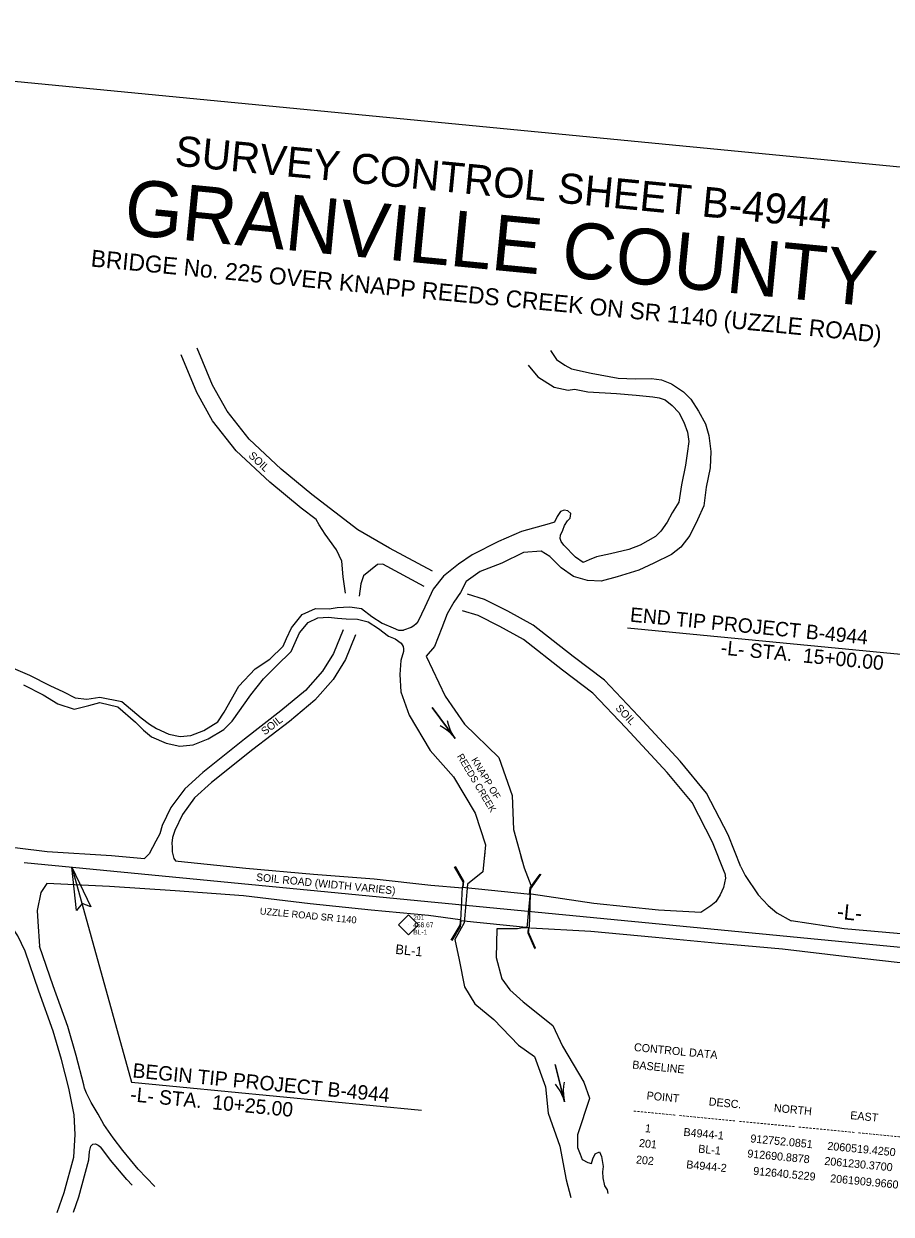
# Model space of a CAD drawing. Extents: x 2060504 to 2061945, y 912229 to 913160.
# Drawn here: x 2061030 to 2061482, y 912540 to 913160 of the extents above; entities that cross this region are included whole.
import ezdxf

# ---------------------------------------------------------------- set-up
doc = ezdxf.new("R2010")
doc.units = 0
for name, color, linetype in [('COGO Default Chain', 7, 'Continuous'), ('CTL Sheet Border CELL', 7, 'Continuous'), ('CTL Sheet Text', 7, 'Continuous'), ('CTL Supplemental Horizontal and Vertical CELL', 7, 'Continuous'), ('CTL Supplemental Horizontal and Vertical Cogo Comment', 7, 'Continuous'), ('CTL Supplemental Horizontal and Vertical Cogo Elevation', 7, 'Continuous'), ('CTL Supplemental Horizontal and Vertical Cogo Number', 7, 'Continuous'), ('CTL Supplemental Horizontal and Vertical Text', 7, 'Continuous'), ('Default', 7, 'Continuous'), ('Exist Horizontal Alignment', 7, 'Continuous'), ('Exist Hydro Jurisdictional Stream or Body of Water', 7, 'Continuous'), ('Exist Hydro Stream or Body of Water', 7, 'Continuous'), ('Exist PHM Water Shape', 7, 'Continuous'), ('Exist Roads Soil', 7, 'Continuous'), ('Exist Roads Soil Text', 7, 'Continuous'), ('Exist Structure Major Bridge WW', 7, 'Continuous'), ('Exist Structure Major Deck Tunnel Box Culvert', 7, 'Continuous'), ('Prop Terminator CELL', 7, 'Continuous'), ('Sheet Data Field CELL', 7, 'Continuous')]:
    doc.layers.add(name, color=color, linetype=linetype)

# ---------------------------------------------------------------- blocks, each defined once
blk = doc.blocks.new('EXIST HYDRO RIVER FLOW ARROW')
at = {"layer": 'Default'}
blk.add_line((0, 0), (0, 0), dxfattribs=at)
blk.add_lwpolyline([(0, 0.04575), (0.03775, 0.03), (0.07725, 0.01725), (0.118, 0.00775), (0.159, 0.0015), (0.2, 0), (-0.2, 0), (0.2, 0), (0.159, -0.0015), (0.118, -0.00775), (0.07725, -0.01725), (0.03775, -0.03), (0, -0.04575)], dxfattribs=at)

msp = doc.modelspace()

# ---------------------------------------------------------------- linework, layer by layer
at = {"layer": 'COGO Default Chain'}
msp.add_line((2061030.33, 912723.42), (2061621.2, 912666.3), dxfattribs=at)
at = {"layer": 'CTL Sheet Border CELL'}
msp.add_lwpolyline([(2061883, 913047.03), (2060714.54, 913159.97), (2060635.47, 912342.05), (2061803.94, 912229.1)], close=True, dxfattribs=at)
at = {"layer": 'CTL Supplemental Horizontal and Vertical CELL'}
msp.add_line((2061230.37, 912690.89), (2061230.37, 912690.89), dxfattribs=at)
msp.add_lwpolyline([(2061225.16, 912690.91), (2061230.4, 912696.15), (2061235.65, 912690.9), (2061230.41, 912685.66)], close=True, dxfattribs=at)
at = {"layer": 'Exist Horizontal Alignment'}
msp.add_line((2061030.33, 912723.42), (2061621.2, 912666.3), dxfattribs=at)
at = {"layer": 'Exist Hydro Jurisdictional Stream or Body of Water'}
for points in [[(2061304.42, 912989.92), (2061307.54, 912985.21), (2061311.82, 912982.35), (2061315.34, 912980.44), (2061325.46, 912978.15), (2061339.51, 912975.44), (2061348.55, 912975.2), (2061356.88, 912975.38), (2061362.21, 912974.71), (2061367.28, 912972.49), (2061373.57, 912968.41), (2061377.35, 912964.63), (2061381.47, 912958.32), (2061385.06, 912951.64), (2061386.79, 912945.66), (2061387.76, 912937.35), (2061387.52, 912928.81), (2061385.39, 912918.75), (2061384.14, 912909.07), (2061380.97, 912901.67), (2061376.92, 912893.61), (2061372.18, 912887.44), (2061367.4, 912883.66), (2061358.23, 912879.2), (2061350.28, 912875.6), (2061339.1, 912872.15), (2061330.73, 912869.8), (2061323.62, 912870.25), (2061316.37, 912872.25), (2061309.97, 912876.82), (2061304.07, 912882.6), (2061299.52, 912885.49), (2061290.35, 912884.82), (2061279.03, 912879.14), (2061267.8, 912874.87), (2061260.5, 912869.71), (2061257.49, 912863.9), (2061254.01, 912858.95), (2061250.54, 912852.73), (2061247.8, 912845.5), (2061243.96, 912835.84), (2061239.71, 912830.79), (2061249.44, 912809.94)], [(2061292.78, 912982.22), (2061297.82, 912976.25), (2061306.31, 912970.77), (2061313.49, 912969.29), (2061316.86, 912969.71), (2061323.87, 912968.32), (2061338.79, 912967.46), (2061349.03, 912966.7), (2061357.56, 912965.7), (2061360.86, 912965.19), (2061363.99, 912964.18), (2061367.63, 912961.35), (2061371.24, 912957.71), (2061373.7, 912952.61), (2061375.6, 912947.36), (2061376.34, 912942.47), (2061375.54, 912936.27), (2061374.61, 912930.26), (2061372.52, 912920.03), (2061371.17, 912911), (2061367.65, 912905.32), (2061365.03, 912900.55), (2061361.82, 912895.77), (2061358.97, 912893.01), (2061351.07, 912888.53), (2061345.07, 912886.25), (2061335.63, 912883.97), (2061328.39, 912882.57), (2061324.51, 912880.84), (2061321.36, 912879.57), (2061317.46, 912882.26), (2061311.25, 912888.61), (2061309.97, 912890.39), (2061309.4, 912892.04), (2061309.62, 912893.77), (2061310.71, 912896.31), (2061311.59, 912898.82), (2061313.14, 912901.22), (2061314.63, 912902.66), (2061314.88, 912905), (2061313.41, 912906.43), (2061311.48, 912906.71), (2061309.57, 912906.04), (2061307.82, 912903.42), (2061306.45, 912900.55), (2061303.59, 912899.73), (2061289.23, 912895.74), (2061277.29, 912890.45), (2061263.65, 912883.57), (2061256.5, 912878.71), (2061248.58, 912872.42), (2061243.24, 912865.71), (2061238.87, 912856.23), (2061235.44, 912849.05), (2061234.38, 912847.57)], [(2061014.35, 912828.84), (2061033.04, 912820.93), (2061043.62, 912815.46), (2061050.74, 912812.26), (2061056.95, 912809.15), (2061062.9, 912808.46), (2061069.77, 912809.46), (2061081.18, 912807.13), (2061091.23, 912798.73), (2061095.59, 912795.43), (2061099.24, 912793.06), (2061105.74, 912790.15), (2061111.58, 912788.95), (2061117.19, 912789.51), (2061123.89, 912792.12), (2061131.22, 912796.59), (2061134.39, 912801.56), (2061142.12, 912815.13), (2061150.54, 912824.12), (2061158.29, 912829.28), (2061165.13, 912836.06), (2061166.88, 912839.91), (2061169.48, 912845.61), (2061175.05, 912852.43), (2061182.09, 912855.52), (2061189.19, 912855.36), (2061193.24, 912856.16), (2061199.82, 912856.53), (2061205.99, 912855.6), (2061211.3, 912851.5), (2061216.75, 912847.89), (2061222.49, 912845.48), (2061225.31, 912844.38), (2061227.89, 912844.39)], [(2061029.97, 912815.9), (2061040.31, 912810.63), (2061047.78, 912806.01), (2061056.31, 912803.11), (2061064.07, 912805.08), (2061069.72, 912806.67), (2061079.13, 912804.41), (2061088.22, 912796.47), (2061092.42, 912792.25), (2061096.62, 912788.82), (2061104.21, 912785.41), (2061111.33, 912783.96), (2061118.36, 912784.66), (2061126.09, 912787.68), (2061134.25, 912792.65), (2061138.64, 912796.89), (2061148.33, 912810.68), (2061154.87, 912819.05), (2061161.76, 912825.76), (2061169.26, 912833.2), (2061171.37, 912837.86), (2061173.71, 912842.98), (2061178.13, 912848.38), (2061183.31, 912850.66), (2061188.82, 912851.09), (2061193.53, 912850.53), (2061198.04, 912850.21), (2061203.92, 912850.06), (2061209.45, 912848.69), (2061214.73, 912845.17), (2061219.97, 912841.13), (2061223.47, 912839.79), (2061226.62, 912837.47)], [(2061226.62, 912837.47), (2061227.59, 912835.83), (2061227.91, 912834.64), (2061227.77, 912833.17)], [(2061227.77, 912833.17), (2061226.42, 912828.49), (2061225.86, 912821.31), (2061226.47, 912812.15), (2061230.85, 912800.08)], [(2061249.44, 912809.94), (2061259.59, 912795.35), (2061277.43, 912778.04), (2061284.45, 912758.16), (2061285.07, 912740.61), (2061290.6, 912720.54), (2061294.17, 912711.64), (2061292.06, 912689.41), (2061289.73, 912689.28), (2061287.13, 912688.9), (2061276.35, 912688.89), (2061276.03, 912673.92), (2061279.1, 912662.87), (2061283.26, 912657.14), (2061290.13, 912650.75), (2061305.62, 912638.46), (2061310.54, 912627.68), (2061321.66, 912609), (2061324.73, 912600.71)], [(2061230.85, 912800.08), (2061241.79, 912781.69), (2061253.93, 912767.88), (2061265.22, 912749.03), (2061270.49, 912732.47), (2061269.15, 912718.44), (2061261.19, 912712.07), (2061259.41, 912692.02), (2061254.6, 912683.23), (2061256.75, 912672.67), (2061259.51, 912658.65), (2061265.02, 912649.85), (2061274.93, 912641.7), (2061287.62, 912628.21), (2061296.1, 912622.37), (2061301.68, 912606.52), (2061303.06, 912592.92)], [(2061270.13, 912728.64), (2061269.82, 912725.38)], [(2061288.98, 912726.44), (2061289.8, 912723.45)], [(2061324.73, 912600.56), (2061318.39, 912581.55), (2061318.36, 912575.07), (2061319.76, 912571.52), (2061320.93, 912568.81), (2061323.83, 912567.13), (2061325.79, 912566.67), (2061326.38, 912569.08), (2061327.56, 912571.76), (2061329.86, 912572.82), (2061330.98, 912570.36), (2061331.72, 912565.15), (2061331.51, 912562.28), (2061331.52, 912559.12), (2061332.48, 912554.96), (2061333.88, 912552.89), (2061334.17, 912551.12)], [(2061303.06, 912592.92), (2061309.23, 912575.73), (2061312.59, 912558.09), (2061314.88, 912548.96), (2061314.88, 912548.91)]]:
    msp.add_lwpolyline(points, dxfattribs=at)
at = {"layer": 'Exist Hydro Stream or Body of Water'}
msp.add_lwpolyline([(2061234.38, 912847.57), (2061233.21, 912846.63), (2061231.82, 912845.77), (2061227.89, 912844.39)], dxfattribs=at)
at = {"layer": 'Exist Roads Soil'}
for p, q in [((2061294, 912689.28), (2061325.36, 912687.64)), ((2061325.36, 912687.64), (2061358.98, 912684.46)), ((2061358.98, 912684.46), (2061391.87, 912681.43)), ((2061391.87, 912681.43), (2061425.16, 912678.44)), ((2061425.16, 912678.44), (2061458.76, 912674.47)), ((2061458.76, 912674.47), (2061493.97, 912670.51))]:
    msp.add_line(p, q, dxfattribs=at)
for points in [[(2061242.91, 912875.03), (2061220.49, 912887.05), (2061203.97, 912896.59), (2061180.13, 912914.92), (2061164.2, 912928.18), (2061147.4, 912943.73), (2061135.97, 912958.28), (2061128.42, 912971.88), (2061120.48, 912991.13)], [(2061182.34, 912901.87), (2061174.5, 912907.9), (2061158.26, 912921.42), (2061140.77, 912937.61), (2061128.45, 912953.28), (2061120.3, 912967.97), (2061112.16, 912987.7)], [(2061197.56, 912863.51), (2061196.42, 912872.13), (2061195.77, 912880.21), (2061192.91, 912886.15), (2061186.97, 912894.36), (2061183.96, 912899.06), (2061182.34, 912901.87)], [(2061217.04, 912878.69), (2061214.25, 912878.57), (2061207.06, 912872.58), (2061205.54, 912868.35), (2061204.72, 912862.01)], [(2061238.65, 912867.09), (2061217.04, 912878.69)], [(2061403.48, 912721.06), (2061396.9, 912737.77), (2061385.58, 912759.51), (2061371.85, 912776.13), (2061350.09, 912799.55), (2061332.48, 912818.25), (2061316.14, 912830.65), (2061295.3, 912846.97), (2061282.15, 912854.19), (2061269.98, 912860.29), (2061261.11, 912862.97)], [(2061395.1, 912717.76), (2061388.7, 912734.03), (2061378.03, 912754.51), (2061365.08, 912770.2), (2061343.52, 912793.4), (2061326.45, 912811.53), (2061310.65, 912823.52), (2061290.32, 912839.43), (2061277.97, 912846.22), (2061266.64, 912851.9), (2061258.51, 912854.35)], [(2061196.43, 912844.51), (2061191.43, 912832.21), (2061185.6, 912822.88), (2061176.77, 912812.93), (2061164.04, 912802.29), (2061145.08, 912787.61), (2061123.34, 912770.28), (2061113.91, 912761.69), (2061106.67, 912752.07), (2061102.13, 912742.57), (2061100.91, 912738.35)], [(2061202.91, 912841.88), (2061197.69, 912829.01), (2061191.22, 912818.68), (2061181.67, 912807.89), (2061168.43, 912796.84), (2061149.4, 912782.11), (2061127.88, 912764.95), (2061119.1, 912756.96), (2061112.69, 912748.43), (2061108.7, 912740.07), (2061107.63, 912736.4)], [(2060886.37, 912743.53), (2060918.27, 912740.51), (2060950.89, 912737.85), (2060982.11, 912734.98), (2061011.2, 912732.95), (2061042.39, 912729.02), (2061075.76, 912726.94), (2061092.95, 912725.5)], [(2061100.91, 912738.35), (2061098.86, 912734.41), (2061095.5, 912727.83), (2061092.95, 912725.5)], [(2061107.63, 912736.4), (2061107.24, 912733.36), (2061107.38, 912731.35), (2061107.32, 912728.88), (2061108.2, 912725.46), (2061109.04, 912724.16)], [(2061109.04, 912724.16), (2061110.45, 912724.04), (2061145.78, 912720.44), (2061180.95, 912717.21), (2061212.61, 912714.91), (2061242, 912711.52), (2061258.56, 912710.24)], [(2061395.1, 912717.76), (2061395.46, 912715.16), (2061394.45, 912710.42), (2061392.76, 912706.46), (2061390.39, 912702.82), (2061387.91, 912700.76), (2061382.65, 912697.32)], [(2061403.48, 912721.06), (2061405.78, 912716.63), (2061412.47, 912706.51), (2061417.65, 912701), (2061422.25, 912697.14), (2061429.74, 912693.06)], [(2061257.32, 912693.45), (2061240.88, 912695.82), (2061210.96, 912698.46), (2061179.23, 912701.76), (2061144.51, 912705.99), (2061109.03, 912708.56), (2061074.8, 912710.89), (2061042.14, 912712.4), (2061038.96, 912707.82), (2061037.17, 912698.29), (2061037.52, 912692.66)], [(2061382.65, 912697.32), (2061360.6, 912698.53), (2061326.96, 912702.01), (2061294.28, 912706.8)], [(2061037.52, 912692.66), (2061038.34, 912679.8)], [(2061457.3, 912688.8), (2061429.74, 912693.06)], [(2061030.78, 912677.17), (2061026.96, 912685.13), (2061023.03, 912691.3)], [(2061616.65, 912673.35), (2061595.6, 912675.15), (2061562.27, 912678.91), (2061528.97, 912682.23), (2061494.66, 912685.54), (2061457.3, 912688.8)], [(2061061.77, 912605.8), (2061061.4, 912607.61), (2061057.44, 912622.9), (2061053.14, 912638.05), (2061045.52, 912659.13), (2061038.34, 912679.8)], [(2061047.6, 912541.15), (2061051.09, 912551.62), (2061056.14, 912569.88), (2061056.84, 912581.68), (2061056.45, 912592.08), (2061053.6, 912605.8), (2061049.71, 912620.8), (2061045.52, 912635.6), (2061037.98, 912656.46), (2061030.78, 912677.17)], [(2061076.73, 912579.99), (2061071.86, 912586.96), (2061068.88, 912592.37), (2061065.25, 912598.46), (2061062.85, 912603.23), (2061061.77, 912605.8)], [(2061064.33, 912572.94), (2061065.08, 912575.72), (2061066.06, 912576.67), (2061067.55, 912576.87), (2061068.79, 912576.26), (2061070.32, 912575.2)], [(2061086.53, 912555.45), (2061083.71, 912558.39), (2061075.35, 912568.46), (2061070.32, 912575.2)], [(2061098.41, 912554.63), (2061089.68, 912563.73), (2061081.64, 912573.41), (2061076.73, 912579.99)], [(2061056.1, 912541.36), (2061058.74, 912549.29), (2061064.07, 912568.56), (2061064.33, 912572.94)]]:
    msp.add_lwpolyline(points, dxfattribs=at)
at = {"layer": 'Exist Structure Major Bridge WW'}
for p, q in [((2061258.94, 912713.21), (2061254.41, 912721.1)), ((2061259.24, 912713.69), (2061254.85, 912721.35)), ((2061293.83, 912710.19), (2061298.94, 912717.37)), ((2061294, 912709.56), (2061299.35, 912717.08)), ((2061298.94, 912717.37), (2061299.35, 912717.08)), ((2061258.66, 912710.52), (2061258.99, 912713.72)), ((2061258.91, 912710.49), (2061259.24, 912713.69)), ((2061258.99, 912713.72), (2061259.24, 912713.69)), ((2061293.38, 912706.88), (2061293.83, 912710.19)), ((2061293.63, 912706.86), (2061294.08, 912710.16)), ((2061293.83, 912710.19), (2061294.08, 912710.16)), ((2061257.31, 912690.05), (2061257.58, 912693.1)), ((2061257.56, 912690.03), (2061257.83, 912693.08)), ((2061252.71, 912682.97), (2061257.36, 912690.67)), ((2061253.14, 912682.71), (2061257.56, 912690.03)), ((2061257.31, 912690.05), (2061257.56, 912690.03)), ((2061292.65, 912686.52), (2061292.93, 912689.57)), ((2061296.17, 912678.56), (2061292.65, 912686.52)), ((2061292.65, 912686.52), (2061292.9, 912686.5)), ((2061292.9, 912686.5), (2061293.18, 912689.55)), ((2061296.63, 912678.76), (2061292.96, 912687.07)), ((2061296.17, 912678.56), (2061296.63, 912678.76))]:
    msp.add_line(p, q, dxfattribs=at)
at = {"layer": 'Exist Structure Major Deck Tunnel Box Culvert'}
msp.add_line((2061258.41, 912710.55), (2061293.98, 912706.82), dxfattribs=at)
msp.add_lwpolyline([(2061258.41, 912710.55), (2061257.47, 912693.11), (2061293.48, 912689.52), (2061293.98, 912706.82)], dxfattribs=at)
msp.add_lwpolyline([(2061258.41, 912710.55), (2061257.47, 912693.11), (2061293.48, 912689.52), (2061293.98, 912706.82)], dxfattribs=at)
at = {"layer": 'Prop Terminator CELL'}
msp.add_lwpolyline([(2061057.5, 912698.29), (2061055.22, 912721.01), (2061065.12, 912700.28), (2061060.49, 912701.98)], close=True, dxfattribs=at)
at = {"layer": 'Sheet Data Field CELL'}
for p, q in [((2061344.47, 912845.53), (2061486.76, 912831.77)), ((2061055.22, 912721.01), (2061086.28, 912609.03)), ((2061086.28, 912609.03), (2061237.16, 912594.44))]:
    msp.add_line(p, q, dxfattribs=at)

# ---------------------------------------------------------------- block references
at = {"layer": 'Exist PHM Water Shape', "xscale": 50.00000000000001}
for p, yscale, rotation in [((2061248.72, 912795.94), 50.00000000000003, -53.392905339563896), ((2061309.26, 912608.44), 50.000000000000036, -75.96373668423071)]:
    msp.add_blockref('EXIST HYDRO RIVER FLOW ARROW', p, dxfattribs=dict(at, yscale=yscale, rotation=rotation))

# ---------------------------------------------------------------- texts
at = {"layer": 'CTL Sheet Border CELL'}
msp.add_text('SURVEY CONTROL SHEET B-4944', height=15.6522, rotation=354.4787, dxfattribs=at).set_placement((2061108.34, 913086.24))
at = {"layer": 'CTL Sheet Text'}
for s, height, p in [('CONTROL DATA', 4.1667, (2061347.68, 912625.26)), ('BASELINE', 4.167, (2061346.8, 912616.14)), ('    POINT          DESC.           NORTH             EAST          ELEVATION           L STATION       OFFSET', 4.16667, (2061348.09, 912600.65)), ('------------ ---------------- ---------------- ---------------- ---------------- ---------------- ----------------', 4.16667, (2061347.29, 912592.36)), ("     1           B4944-1         912752.0851     2060519.4250        487.12'          OUTSIDE PROJECT LIMITS                 ", 4.16667, (2061345.7, 912583.76)), ("   201              BL-1         912690.8878     2061230.3700        458.67'         12+02.24        13.13' RT", 4.16667, (2061345.68, 912575.77)), ("   202           B4944-2         912640.5229     2061909.9660        495.57'          OUTSIDE PROJECT LIMITS                 ", 4.16667, (2061344.09, 912567.17))]:
    msp.add_text(s, height=height, rotation=354.4787, dxfattribs=at).set_placement(p)
at = {"layer": 'CTL Supplemental Horizontal and Vertical Cogo Comment'}
msp.add_text('BL-1', height=2.5, dxfattribs=at).set_placement((2061232.87, 912685.89))
at = {"layer": 'CTL Supplemental Horizontal and Vertical Cogo Elevation'}
msp.add_text('458.67', height=2.5, dxfattribs=at).set_placement((2061232.87, 912689.64))
at = {"layer": 'CTL Supplemental Horizontal and Vertical Cogo Number'}
msp.add_text('201', height=2.5, dxfattribs=at).set_placement((2061232.87, 912693.39))
at = {"layer": 'CTL Supplemental Horizontal and Vertical Text'}
msp.add_text('BL-1', height=5, rotation=354.47872, dxfattribs=at).set_placement((2061223.43, 912675.81))
at = {"layer": 'Exist PHM Water Shape'}
for s, p in [('REEDS CREEK', (2061255.53, 912778.66)), ('KNAPP OF', (2061262.97, 912776.74))]:
    msp.add_text(s, height=3.6, rotation=300.93719, dxfattribs=at).set_placement(p)
at = {"layer": 'Exist Roads Soil Text'}
for s, rotation, p in [('SOIL', 317.21806, (2061146.83, 912934.73)), ('SOIL', 313.27783, (2061337.9, 912803.45)), ('SOIL', 37.73639, (2061155.64, 912789.47)), ('SOIL ROAD (WIDTH VARIES)', 354.38389, (2061151, 912713.82))]:
    msp.add_text(s, height=4, rotation=rotation, dxfattribs=at).set_placement(p)
at = {"layer": 'Sheet Data Field CELL'}
for s, height, rotation, p in [('GRANVILLE COUNTY', 29.0306, 354.4787, (2061081.65, 913050.49)), ('BRIDGE No. 225 OVER KNAPP REEDS CREEK ON SR 1140 (UZZLE ROAD)', 8.8181, 354.4787, (2061064.78, 913033.66)), ('END TIP PROJECT B-4944', 7.5, 354.4787, (2061345.53, 912848.78)), ('-L- STA.  15+00.00', 7.5, 354.4787, (2061392.81, 912831.65)), ('UZZLE ROAD SR 1140', 3.6, 354.55648, (2061152.9, 912696.36)), ('-L-', 8, 354.4787, (2061453.23, 912694.07)), ('BEGIN TIP PROJECT B-4944', 7.5, 354.4787, (2061086.52, 912611.51)), ('-L- STA.  10+25.00', 7.5, 354.4787, (2061085.32, 912599.07))]:
    msp.add_text(s, height=height, rotation=rotation, dxfattribs=at).set_placement(p)

doc.saveas('drawing.dxf')
